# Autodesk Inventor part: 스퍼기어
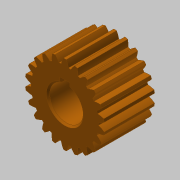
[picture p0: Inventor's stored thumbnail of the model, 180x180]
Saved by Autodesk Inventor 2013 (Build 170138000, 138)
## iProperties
Created: 2019-03
Part Number: 스퍼기어
Material: 강철
Document SubType Name: Modeling
Designer: mduedu
Categories: <?xml version="1.0" encoding="UTF-16"?> <MemberInstance><Categories><FamilyTemplate><FamilyTemplateParameter ValueType="xs:double" Id="1" ObjectReferenceKey="da
Density: 1 g/cm^3
CustomPartVersion: 1
Author: mduedu
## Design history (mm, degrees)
sketch "Sketch1"
  geometry: C1 r 23.6 at (0, 0)
  constraints: 1 centre point
  dimensions: "d0" = 47.2 diameter of C1 (= da_da)
extrude "Extrusion1" new body sketch "Sketch1" distance "d1" = 30 (= da_b); taper "d2" = 0 deg
workplane "Work Plane2"
sketch "Sketch2"
  geometry: C1 r 23.6 at (0, 0) reference; C2 r 22 at (0, 0)
  constraints: 1 centre point, 1 coincident
  dimensions: "d3" = 44 diameter of C2 (= da_dw)
feature "피치 지름" sketch "Sketch2" dims "d4" = 10, "d5" = 0
workplane "Work Plane8"
workplane "Work Plane9"
feature "스퍼 기어" dims "da_b" = 30, "da_d" = 44, "da_aw" = 44, "da_da" = 47.2, "da_df" = 40.172, "da_dw" = 44, angle "da_beta" = 0 deg, "da_lefttooth" = 0, "da_righttooth" = 0
sketch "스케치3"
  geometry: L1 (-3, 9.539)-(3, 9.539); L2 (3, 9.539)-(3, 12.8); L3 (3, 12.8)-(-3, 12.8); L4 (-3, 12.8)-(-3, 9.539); A1 r 10 centre (0, 0) between (-3, 9.539) and (3, 9.539); 1 further point
  constraints: 8 end point, 2 parallel, 2 point on circle, 1 centre point, 1 coincident, 1 horizontal, 1 perpendicular
  dimensions: "d49" = 20 diameter of A1; "d50" = 6 distance of L2.end L3.end; "d51" = 22.8 dimension on A1 L3
extrude "돌출2" cut sketch "스케치3" stored distance "d52" = 10; taper "d53" = 0 deg
chamfer "모따기1" distance "d54" = 1; stored, may be unused: second distance "d55" = 2, angle "d56" = 45 deg
body "Solid1"
body "Srf1"
other parameters: "d16" = 44 (= da_aw), "d17" = 0, "d34" = 1.428 (computed from da_z), "d39" = 0, "d41" = 0, "d43" = 44 (= da_aw), "d46" = 44 (= da_aw), "d47" = 0, "d48" = 0
